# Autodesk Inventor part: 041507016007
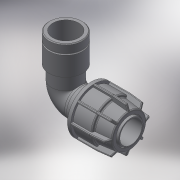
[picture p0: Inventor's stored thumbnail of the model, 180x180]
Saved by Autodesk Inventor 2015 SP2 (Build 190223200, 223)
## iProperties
Created: 2017-08
Part Number: 041507016007
Material: Generic
Description: PLASSON IRRIFIT ELBOW 16F-3/4"F
Document SubType Name: Modeling
Designer: KIM
Density: 1 g/cm^3
Appearance: Default
Author: KIM
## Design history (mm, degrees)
derived "041507.ipt"
feature "Solid1::041507.ipt"
tag "TaggingFeature1"
body "Solid1"
other parameters: "d5" = 28.8, "d6" = 12.8, "d10" = 34, "d22" = 22.4, "d24" = 2.4, "d25" = 30.6, "d26" = 27.2, "d31" = 0.8, "d49" = 1.7, "d50" = 0, "d58" = 0.48, "d61" = 360 deg, "d77" = 16, "d78" = 6 deg, "d80" = 17.6, "d81" = 47, "d82" = 2.4, "d84" = 5 deg, "d85" = 70 deg, "d86" = 32.3, "d87" = 0.48, "d88" = 0, "d100" = 27.2, "d101" = 8, "d102" = 0, "d103" = 31.3521, "d107" = 16, "d108" = 21.7053, "d109" = 17, "d110" = 24.117, "d113" = 0.72351, "d120" = 9.4, "d121" = 9.4, "d122" = 47, "d123" = 21.7053, "d124" = 2.35, "d125" = 90 deg, "d126" = 31.3521, "d127" = 0.72351, "d128" = 6.8, "d129" = 100 deg, "d130" = 22.1, "d_" = 16, "E_" = 34, "A_" = 47, "l_" = 16, "A_1" = 47, "l_2" = 17, "G_" = 24.117, "d99" = 22.4
